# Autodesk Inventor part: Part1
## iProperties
Author: Renu Muthoo
Created: 2001-11
Part Number: Part1
Document SubType Name: Modeling
Designer: Renu Muthoo
Control State: 0
Master: False
Checked Out: False
PropertySet Name: Design Tracking Control
Shininess: 64.0
Angle Display Precision: 2
Document Length Units: 11269
Document Angle Units: 11283
Document Time Units: 11279
Document Mass Units: 11290
Document Length Units Precision: 3
Document Angle Units Precision: 2
Compacted: False
PropertySet Name: _Private Model Information
Density: 0.0
Volumn: 0.0
Area: 0.0
PropertySet Name: Model Information
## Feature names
1. Extrusion1
2. Extrusion2
